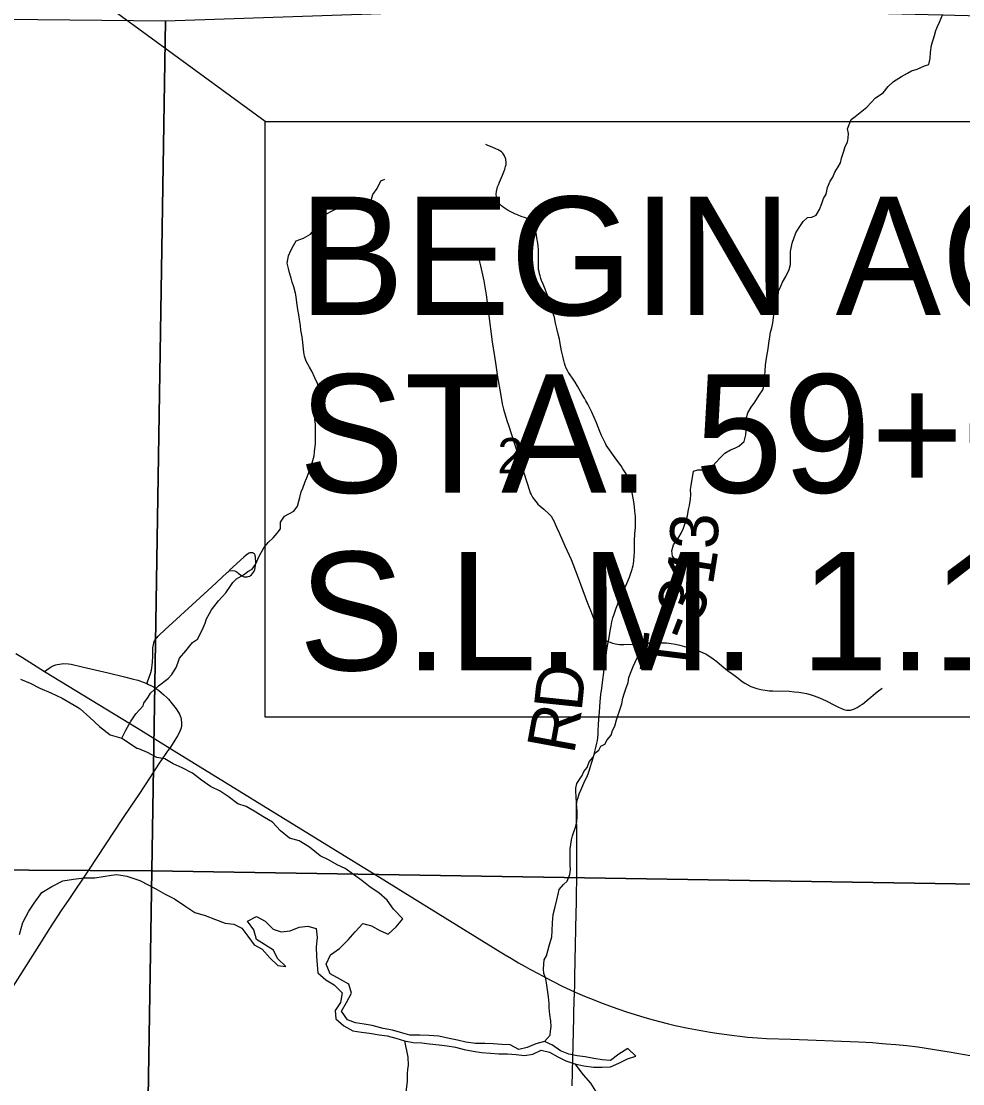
# Model space of a CAD drawing. Extents: x 0 to 34, y 0 to 22.
# Drawn here: x 23.087 to 24.201, y 15.371 to 16.628 of the extents above; entities that cross this region are included whole.
import ezdxf

# ---------------------------------------------------------------- set-up
doc = ezdxf.new("R2010")
doc.units = 0
for name, color, linetype in [('GM_X_Corporation', 7, 'Continuous'), ('GM_X_County_Road', 7, 'Continuous'), ('GM_X_Major_Lake', 7, 'Continuous'), ('GM_X_Major_River', 7, 'Continuous'), ('GM_X_Minor_River', 7, 'Continuous'), ('GM_X_Section_Text', 7, 'Continuous'), ('GM_X_Township_Road', 7, 'Continuous'), ('GM_X_Township_Road_Text', 7, 'Continuous'), ('GM_X_US_Route', 7, 'Continuous'), ('SH_Text', 7, 'Continuous')]:
    doc.layers.add(name, color=color, linetype=linetype)

msp = doc.modelspace()

# ---------------------------------------------------------------- linework, layer by layer
at = {"layer": 'GM_X_Corporation'}
for points in [[(22.2392, 16.6385), (23.2579, 16.628), (23.2418, 15.623), (22.2224, 15.6282)], [(23.2579, 16.628), (23.7676, 16.6453), (24.2698, 16.6327), (24.2658, 16.4792), (24.2407, 15.6067), (23.2418, 15.623)], [(22.2224, 15.6282), (23.2418, 15.623), (23.2254, 14.5998), (22.2045, 14.6168)], [(23.2418, 15.623), (24.2407, 15.6067), (24.2392, 15.4615), (24.2269, 14.5903), (23.2254, 14.5998)]]:
    msp.add_lwpolyline(points, close=True, dxfattribs=at)
at = {"layer": 'GM_X_County_Road'}
for points in [[(23.1352, 15.5758), (23.1379, 15.5799), (23.1441, 15.589), (23.1673, 15.6235), (23.2077, 15.6846), (23.2176, 15.6992), (23.2268, 15.713), (23.2401, 15.7336), (23.2502, 15.7488), (23.2631, 15.7678)], [(23.0733, 15.4785), (23.1115, 15.5389), (23.1206, 15.5533), (23.1352, 15.5758)]]:
    msp.add_lwpolyline(points, dxfattribs=at)
at = {"layer": 'GM_X_Major_Lake'}
for points in [[(23.0865, 15.8494), (23.0979, 15.8446), (23.1093, 15.839), (23.1226, 15.8335), (23.136, 15.8272), (23.1547, 15.816)], [(23.1547, 15.816), (23.1573, 15.8145), (23.1684, 15.8043), (23.1798, 15.7934)], [(23.1798, 15.7934), (23.1928, 15.7837), (23.2065, 15.7797), (23.2249, 15.7676)], [(23.5589, 15.4283), (23.5468, 15.4285), (23.5358, 15.4315), (23.5263, 15.4344), (23.5152, 15.4363), (23.5023, 15.4399), (23.4928, 15.4414), (23.4826, 15.4432), (23.4731, 15.4465), (23.4662, 15.4567), (23.4722, 15.467), (23.4778, 15.4781), (23.4746, 15.4887), (23.4651, 15.4943), (23.4529, 15.5011), (23.4479, 15.5124), (23.4531, 15.5235), (23.4637, 15.5311), (23.4738, 15.5411), (23.4821, 15.5507), (23.4915, 15.5606), (23.5014, 15.5577), (23.5113, 15.5521), (23.5212, 15.548), (23.5309, 15.5564), (23.5388, 15.566), (23.5277, 15.5773), (23.5201, 15.5882), (23.5102, 15.5969), (23.4999, 15.6036), (23.4903, 15.6115), (23.4804, 15.6183), (23.4705, 15.6254), (23.461, 15.6299), (23.4507, 15.6359), (23.4408, 15.6407), (23.4282, 15.6509), (23.416, 15.6584), (23.4046, 15.6613), (23.394, 15.6703), (23.3844, 15.6805), (23.3749, 15.6857), (23.3627, 15.6932), (23.3532, 15.6988), (23.3437, 15.7022), (23.3322, 15.7108), (23.3227, 15.7172), (23.3113, 15.7224), (23.3006, 15.7299), (23.2899, 15.7382), (23.2778, 15.7445), (23.2671, 15.7494), (23.2572, 15.7554), (23.2477, 15.7568), (23.2367, 15.7628), (23.2264, 15.7669), (23.2249, 15.7676)], [(23.1943, 15.6176), (23.2003, 15.6186), (23.2125, 15.6165), (23.2277, 15.6112)], [(23.0854, 15.5476), (23.0895, 15.5617), (23.0965, 15.5751), (23.1029, 15.5846), (23.1119, 15.5972), (23.1236, 15.6042), (23.1368, 15.6108), (23.1492, 15.6128), (23.1617, 15.6144), (23.1746, 15.6146), (23.1943, 15.6176)], [(23.2277, 15.6112), (23.2467, 15.6015), (23.2578, 15.5951), (23.2688, 15.5899), (23.281, 15.5816), (23.2928, 15.5734), (23.305, 15.5701), (23.3171, 15.5652), (23.3285, 15.5608), (23.3388, 15.5597), (23.3483, 15.5552), (23.3552, 15.5454), (23.3629, 15.5352), (23.3724, 15.53), (23.3812, 15.5198), (23.3907, 15.5108), (23.4002, 15.5097), (23.3906, 15.5191), (23.3856, 15.529), (23.3658, 15.5417), (23.3623, 15.5531), (23.355, 15.5633), (23.3656, 15.5687), (23.3759, 15.5631), (23.3854, 15.554), (23.3949, 15.5507), (23.4055, 15.5519), (23.4161, 15.5562), (23.4263, 15.5574), (23.4362, 15.5545), (23.4374, 15.5438), (23.436, 15.5328), (23.4365, 15.5214), (23.4373, 15.5116), (23.4382, 15.5021), (23.4477, 15.4938), (23.4576, 15.4882), (23.4668, 15.4784), (23.465, 15.4673), (23.4586, 15.4578), (23.4594, 15.4479), (23.469, 15.4397), (23.4796, 15.4337), (23.4899, 15.4322), (23.4994, 15.4308), (23.5108, 15.429), (23.5202, 15.4276), (23.5305, 15.425), (23.5404, 15.4217), (23.551, 15.4198), (23.5609, 15.4196), (23.5703, 15.4181), (23.5817, 15.4171), (23.5912, 15.416), (23.6007, 15.4142), (23.611, 15.4116), (23.6216, 15.4094), (23.6318, 15.408), (23.6421, 15.407), (23.6523, 15.4063), (23.6622, 15.4064), (23.6728, 15.4057), (23.6823, 15.4046), (23.6925, 15.4059), (23.7023, 15.4109), (23.7122, 15.4083), (23.7217, 15.4027), (23.7312, 15.3982), (23.7418, 15.3945)], [(23.7418, 15.3945), (23.7525, 15.3923), (23.7642, 15.3905), (23.7741, 15.3906), (23.7843, 15.3911), (23.7941, 15.3953), (23.8043, 15.4004), (23.8142, 15.4035), (23.8046, 15.4129), (23.794, 15.406), (23.7843, 15.3987), (23.7744, 15.3993), (23.7645, 15.4008), (23.7543, 15.403), (23.7448, 15.404), (23.7349, 15.4062), (23.725, 15.4099), (23.7155, 15.4167), (23.706, 15.4208), (23.6958, 15.4184), (23.6856, 15.4138), (23.6758, 15.4114), (23.6655, 15.417), (23.6556, 15.4173), (23.6454, 15.4184), (23.6355, 15.4187), (23.6245, 15.4186), (23.6132, 15.4204), (23.6033, 15.4226), (23.5934, 15.4244), (23.5813, 15.4273), (23.5695, 15.428), (23.5589, 15.4283)]]:
    msp.add_lwpolyline(points, dxfattribs=at)
at = {"layer": 'GM_X_Major_River'}
msp.add_lwpolyline([(23.7418, 15.3945), (23.7518, 15.3817), (23.7606, 15.3719), (23.7664, 15.3621)], dxfattribs=at)
at = {"layer": 'GM_X_Minor_River'}
for points in [[(23.8791, 16.0679), (23.8787, 16.0736), (23.8794, 16.0786), (23.8805, 16.0858), (23.8813, 16.0904), (23.8824, 16.0953), (23.8873, 16.0972), (23.8942, 16.0972), (23.8999, 16.098), (23.9048, 16.1014), (23.9089, 16.106), (23.9135, 16.1109), (23.9195, 16.1167), (23.926, 16.1205), (23.9313, 16.1228), (23.9358, 16.125), (23.9423, 16.1304), (23.9442, 16.1384), (23.9445, 16.1437), (23.9441, 16.1505), (23.9445, 16.1574), (23.9464, 16.1646), (23.9505, 16.1711), (23.9547, 16.1771), (23.96, 16.1855), (23.9641, 16.1916), (23.966, 16.1977), (23.966, 16.2022), (23.9667, 16.2091), (23.9671, 16.2136), (23.9674, 16.2212), (23.9689, 16.2315), (23.9704, 16.2403), (23.9712, 16.2467), (23.9727, 16.2543), (23.9734, 16.26), (23.9749, 16.265), (23.976, 16.2707), (23.9775, 16.2832), (23.979, 16.2882), (23.9809, 16.2969), (23.9824, 16.3018), (23.9827, 16.3083), (23.9854, 16.3144), (23.9876, 16.3189), (23.9914, 16.3258), (23.9952, 16.3338), (23.9971, 16.3399), (23.9971, 16.3459), (23.997, 16.3554), (23.9989, 16.3649), (24.0034, 16.3771), (24.0072, 16.3836), (24.0121, 16.3908), (24.017, 16.3954), (24.022, 16.3958), (24.0273, 16.3981), (24.0314, 16.4049), (24.0341, 16.4121), (24.0359, 16.4178), (24.039, 16.4231), (24.0408, 16.4311), (24.0438, 16.4384), (24.0469, 16.4433), (24.0495, 16.449), (24.0533, 16.4555), (24.0559, 16.46), (24.0574, 16.4657), (24.0601, 16.4737), (24.0616, 16.4794), (24.0642, 16.4847), (24.0653, 16.4893), (24.0657, 16.4946), (24.0642, 16.5003), (24.0687, 16.5113), (24.0732, 16.5148), (24.0793, 16.5197), (24.0872, 16.5258), (24.0974, 16.5369), (24.1065, 16.5429), (24.1126, 16.5502), (24.1186, 16.5563), (24.1281, 16.562), (24.1353, 16.5662), (24.1399, 16.5688), (24.1467, 16.5708), (24.1554, 16.5746), (24.1603, 16.5765), (24.1622, 16.5833), (24.1626, 16.5905), (24.1637, 16.5993), (24.1671, 16.6107), (24.1689, 16.6164), (24.1708, 16.6213), (24.1731, 16.6263), (24.1769, 16.6358)], [(23.2324, 15.8212), (23.2377, 15.828), (23.2404, 15.833), (23.2499, 15.8417), (23.2612, 15.8501), (23.2654, 15.8551), (23.2707, 15.8634), (23.2726, 15.8684), (23.2744, 15.8745), (23.282, 15.8829), (23.29, 15.8928), (23.296, 15.8966), (23.3013, 15.9076), (23.3051, 15.9156), (23.3066, 15.9209), (23.31, 15.927), (23.3126, 15.9316), (23.3206, 15.9422), (23.3293, 15.9517), (23.3346, 15.959), (23.3376, 15.9639), (23.3421, 15.9681), (23.3501, 15.9727), (23.3554, 15.9769), (23.3603, 15.9796), (23.3645, 15.9849), (23.3686, 15.9948), (23.3743, 16.0047), (23.3796, 16.0111), (23.3853, 16.0168), (23.3902, 16.0222), (23.394, 16.0271), (23.394, 16.0351), (23.3989, 16.0423), (23.4099, 16.0481), (23.414, 16.0542), (23.4155, 16.0599), (23.417, 16.0644), (23.4185, 16.0709), (23.4204, 16.0754), (23.4227, 16.0819), (23.4257, 16.0888), (23.428, 16.0952), (23.4313, 16.1055), (23.4336, 16.1135), (23.434, 16.1184), (23.4355, 16.1283), (23.4354, 16.1511), (23.4346, 16.1564), (23.4346, 16.1625), (23.4353, 16.1705), (23.4368, 16.1758), (23.4387, 16.1804), (23.4402, 16.1853), (23.4402, 16.1925), (23.4379, 16.199), (23.4345, 16.2058), (23.431, 16.2138), (23.4284, 16.2184), (23.4245, 16.2256), (23.4222, 16.2316), (23.4215, 16.2362), (23.4203, 16.2476), (23.4195, 16.2544), (23.418, 16.262), (23.4176, 16.2677), (23.4164, 16.275), (23.4156, 16.2803), (23.4145, 16.2867), (23.4133, 16.2951), (23.4125, 16.3015), (23.4118, 16.3061), (23.4098, 16.3133), (23.4079, 16.319), (23.4064, 16.3236), (23.4045, 16.33), (23.4033, 16.3353), (23.4018, 16.3414), (23.4033, 16.3502), (23.4063, 16.3566), (23.4093, 16.3623), (23.4127, 16.3677), (23.4211, 16.3711), (23.4294, 16.3757), (23.4354, 16.3829), (23.4426, 16.3932), (23.4483, 16.3996), (23.4544, 16.4031), (23.4635, 16.4073), (23.4737, 16.4084), (23.4783, 16.4084), (23.484, 16.4077), (23.4885, 16.4077), (23.495, 16.4115), (23.5014, 16.4172), (23.5033, 16.4225), (23.5082, 16.4298), (23.5127, 16.4389), (23.5173, 16.4408)], [(23.706, 15.4208), (23.713, 15.4285), (23.7133, 15.4331), (23.7141, 15.4388), (23.7137, 15.4449), (23.7125, 15.4529), (23.7117, 15.4608), (23.7117, 15.4658), (23.711, 15.4738), (23.709, 15.4875), (23.7075, 15.4954), (23.7052, 15.5015), (23.7048, 15.5068), (23.7059, 15.5175), (23.7085, 15.5224), (23.7116, 15.5342), (23.7146, 15.5449), (23.7153, 15.5517), (23.7157, 15.5612), (23.716, 15.5666), (23.7164, 15.5711), (23.7183, 15.5787), (23.7205, 15.5886), (23.7224, 15.5951), (23.7235, 15.6008), (23.7285, 15.6065), (23.733, 15.6107), (23.736, 15.6183), (23.7368, 15.6244), (23.7364, 15.6297), (23.7364, 15.635), (23.7363, 15.6487), (23.7371, 15.6541), (23.7382, 15.6594), (23.7393, 15.6643), (23.7431, 15.6757), (23.7442, 15.6807), (23.7449, 15.6864), (23.7449, 15.6929), (23.7438, 15.7027), (23.7434, 15.7111), (23.743, 15.716), (23.743, 15.7206), (23.7445, 15.7259), (23.7505, 15.7354), (23.7528, 15.7404), (23.7566, 15.745), (23.7588, 15.7518), (23.7637, 15.7571), (23.7656, 15.7621), (23.7702, 15.7655), (23.7728, 15.7701), (23.7774, 15.7728), (23.78, 15.7777), (23.7849, 15.7834), (23.7864, 15.7887), (23.7891, 15.7937), (23.7913, 15.8013), (23.794, 15.8097), (23.7959, 15.8154), (23.7974, 15.8203), (23.7989, 15.8272), (23.8004, 15.8321), (23.8022, 15.8382), (23.8049, 15.8454), (23.806, 15.8515), (23.8087, 15.8584), (23.8109, 15.8644), (23.8132, 15.8694), (23.8158, 15.8747), (23.8185, 15.8804), (23.8226, 15.8873), (23.8272, 15.8907), (23.8317, 15.8938), (23.8359, 15.9021), (23.8389, 15.909), (23.8423, 15.9173), (23.8445, 15.9242), (23.8464, 15.9295), (23.8487, 15.9345), (23.8521, 15.9405), (23.8562, 15.9516), (23.8593, 15.9565), (23.8623, 15.9634), (23.8638, 15.9698), (23.8649, 15.9748), (23.8645, 15.9797), (23.8645, 15.9843), (23.8614, 15.99), (23.8576, 15.9949), (23.8568, 16.0014), (23.8587, 16.0082), (23.8648, 16.0174), (23.8678, 16.0223), (23.8704, 16.028), (23.8723, 16.0341), (23.875, 16.0425), (23.8765, 16.0501), (23.8776, 16.055), (23.8787, 16.0622), (23.8791, 16.0679)], [(23.2065, 15.7797), (23.211, 15.7892), (23.2166, 15.799), (23.2229, 15.8085), (23.2316, 15.818), (23.2324, 15.8212)], [(23.5404, 15.4217), (23.5445, 15.4024), (23.5449, 15.3932), (23.5441, 15.3879), (23.5438, 15.383), (23.5438, 15.3735), (23.5419, 15.3582)]]:
    msp.add_lwpolyline(points, dxfattribs=at)
at = {"layer": 'GM_X_Township_Road'}
for points in [[(23.7436, 15.5728), (23.7439, 15.5848), (23.7443, 15.6237), (23.7442, 15.6749), (23.7441, 15.6806), (23.7439, 15.6968), (23.7441, 15.7002), (23.7443, 15.7032), (23.7449, 15.7063), (23.7459, 15.7096), (23.7472, 15.7138), (23.7492, 15.7181), (23.7528, 15.7264), (23.7568, 15.7356), (23.7576, 15.7374), (23.7585, 15.7397), (23.7593, 15.7421), (23.7602, 15.745), (23.762, 15.7512), (23.7639, 15.7576), (23.7656, 15.7639), (23.7668, 15.7686), (23.7681, 15.7739), (23.7686, 15.7768), (23.7691, 15.7803), (23.7695, 15.785), (23.7697, 15.7897), (23.77, 15.7951), (23.7704, 15.8024), (23.7711, 15.8108), (23.7721, 15.8226), (23.7729, 15.8313), (23.7738, 15.8388), (23.775, 15.8488), (23.7761, 15.8572), (23.7772, 15.866), (23.7779, 15.871), (23.779, 15.8779), (23.7803, 15.8866), (23.7811, 15.8908), (23.7817, 15.8946), (23.7828, 15.9013), (23.7837, 15.9067), (23.7848, 15.9124), (23.7858, 15.9172), (23.787, 15.9221), (23.7883, 15.9265), (23.7908, 15.9336), (23.7916, 15.9356), (23.7937, 15.9406), (23.7973, 15.9487), (23.8036, 15.9627), (23.8066, 15.9701), (23.8087, 15.9762), (23.8098, 15.9795), (23.8103, 15.9813), (23.811, 15.9838), (23.8113, 15.9862), (23.8118, 15.9895), (23.8122, 15.9954), (23.8124, 15.9994), (23.8125, 16.0044), (23.8126, 16.0114), (23.8127, 16.0155), (23.8128, 16.0191), (23.813, 16.0218), (23.8133, 16.0252), (23.8135, 16.0288), (23.8137, 16.0325), (23.8138, 16.0366), (23.8136, 16.0418), (23.8131, 16.0482), (23.8126, 16.0533), (23.8118, 16.0593), (23.8111, 16.0634), (23.8102, 16.0677), (23.8093, 16.0717), (23.8083, 16.0757), (23.8073, 16.0796), (23.806, 16.084), (23.8045, 16.0882), (23.8029, 16.0914), (23.8018, 16.0935), (23.8003, 16.0958), (23.7987, 16.0984), (23.7967, 16.1016), (23.7918, 16.1086), (23.7876, 16.1141), (23.7829, 16.1208), (23.7792, 16.1263), (23.7782, 16.1281), (23.7765, 16.1312), (23.7749, 16.1343), (23.7734, 16.1377), (23.7715, 16.1422), (23.7695, 16.1475), (23.7675, 16.1526), (23.7647, 16.159), (23.7619, 16.1654), (23.7597, 16.17), (23.7573, 16.1746), (23.7551, 16.1787), (23.7534, 16.1817), (23.7505, 16.1863), (23.745, 16.1961), (23.7423, 16.2007), (23.7393, 16.2054), (23.7365, 16.2093), (23.7346, 16.2121), (23.7332, 16.2146), (23.7317, 16.2174), (23.7306, 16.2203), (23.7296, 16.223), (23.7289, 16.2262), (23.7277, 16.2314), (23.7264, 16.2378), (23.7247, 16.2465), (23.7237, 16.2515), (23.7223, 16.2575), (23.7207, 16.2643), (23.7193, 16.2706), (23.7178, 16.2773), (23.7167, 16.2808), (23.7115, 16.2977), (23.7082, 16.3076), (23.707, 16.3108), (23.7047, 16.3165), (23.7027, 16.3211), (23.7019, 16.3232), (23.7009, 16.3265), (23.7003, 16.3289), (23.6997, 16.3317), (23.6992, 16.3341), (23.699, 16.3371), (23.699, 16.3544), (23.6989, 16.3577), (23.6985, 16.3617), (23.6982, 16.365), (23.6972, 16.3714), (23.6966, 16.375), (23.6959, 16.3786), (23.6952, 16.3814), (23.6942, 16.384), (23.6931, 16.3863), (23.6921, 16.3882), (23.6908, 16.3899), (23.69, 16.3909), (23.6884, 16.3924), (23.6862, 16.3938), (23.6838, 16.3949), (23.6787, 16.3968), (23.6748, 16.3982), (23.6709, 16.3998), (23.667, 16.4018), (23.6632, 16.4038), (23.6596, 16.4059), (23.6574, 16.4075), (23.6552, 16.4092), (23.6534, 16.4111), (23.6517, 16.4131), (23.6508, 16.4144), (23.65, 16.4162), (23.6496, 16.4177), (23.6492, 16.4199), (23.649, 16.4232), (23.6493, 16.4262), (23.65, 16.4298), (23.6507, 16.4316), (23.6517, 16.4342), (23.6529, 16.4372), (23.654, 16.4399), (23.6564, 16.4455), (23.658, 16.4495), (23.6592, 16.4525), (23.6601, 16.4556), (23.6606, 16.458), (23.6607, 16.4601), (23.6603, 16.4645), (23.6596, 16.4664), (23.6588, 16.4685), (23.6578, 16.4704), (23.6568, 16.4717), (23.6553, 16.4731), (23.6534, 16.4743), (23.6514, 16.4754), (23.6449, 16.4783), (23.6384, 16.4809), (23.6368, 16.4816)], [(23.629, 16.3447), (23.6306, 16.3383), (23.6343, 16.3205), (23.637, 16.3038), (23.64, 16.2823), (23.6443, 16.2483), (23.648, 16.2235), (23.6505, 16.2072), (23.6539, 16.1873), (23.6561, 16.1752), (23.6576, 16.1689), (23.6595, 16.162), (23.6616, 16.1555), (23.6635, 16.1498), (23.6715, 16.1256), (23.6786, 16.1033), (23.6882, 16.0727), (23.6893, 16.0699), (23.6904, 16.0677), (23.6921, 16.0647), (23.6939, 16.0619), (23.6961, 16.059), (23.6983, 16.0566), (23.701, 16.054), (23.7053, 16.0504), (23.7117, 16.0447), (23.7138, 16.0422), (23.716, 16.0386), (23.7174, 16.0359), (23.7189, 16.0328), (23.7204, 16.0294), (23.7235, 16.0224), (23.7303, 16.0073), (23.7378, 15.991), (23.7449, 15.9724), (23.7516, 15.9542), (23.7571, 15.9392), (23.7609, 15.93), (23.7644, 15.9203), (23.7677, 15.9116), (23.7702, 15.9048), (23.7721, 15.9016), (23.774, 15.8992), (23.7756, 15.8976), (23.7771, 15.8963), (23.7787, 15.8953), (23.781, 15.8942), (23.7836, 15.8932), (23.7865, 15.8922), (23.7902, 15.8912), (23.7947, 15.8904), (23.7999, 15.8903), (23.8119, 15.8907), (23.8291, 15.8921), (23.8371, 15.8925), (23.8446, 15.8926), (23.8503, 15.8924), (23.8559, 15.8918), (23.8611, 15.891), (23.8661, 15.8898), (23.8718, 15.8881), (23.8774, 15.8865), (23.8832, 15.8847), (23.8882, 15.883), (23.8929, 15.8812), (23.8974, 15.8789), (23.9016, 15.8763), (23.9054, 15.8735), (23.9097, 15.8703), (23.9156, 15.8652), (23.9226, 15.8598), (23.9288, 15.8553), (23.9349, 15.8508), (23.9399, 15.8468), (23.9431, 15.8446), (23.9464, 15.8427), (23.95, 15.8409), (23.9534, 15.8396), (23.9571, 15.8385), (23.9618, 15.8374), (23.9668, 15.8365), (23.9718, 15.8358), (23.9761, 15.8356), (23.9954, 15.8352), (24.0013, 15.8346), (24.0066, 15.834), (24.0116, 15.8333), (24.016, 15.8324), (24.0203, 15.8313), (24.0251, 15.8298), (24.0313, 15.8273), (24.0392, 15.8239), (24.049, 15.8188), (24.0535, 15.8165), (24.0573, 15.8148), (24.0599, 15.8137), (24.0631, 15.813), (24.0656, 15.8128), (24.0679, 15.813), (24.0702, 15.8135), (24.0725, 15.8143), (24.0757, 15.8159), (24.0795, 15.8184), (24.082, 15.8201), (24.0871, 15.8242), (24.0993, 15.8346), (24.1009, 15.8358), (24.1052, 15.8388)], [(23.236, 15.8442), (23.2379, 15.8494), (23.2406, 15.8573), (23.2413, 15.86), (23.2418, 15.863), (23.2423, 15.8659), (23.2426, 15.8694), (23.2429, 15.8766), (23.2432, 15.8867), (23.2441, 15.8921), (23.2443, 15.8928), (23.2452, 15.8949), (23.2459, 15.8961), (23.2492, 15.9004), (23.25, 15.9013), (23.2572, 15.908), (23.3129, 15.9586), (23.3242, 15.9692), (23.3315, 15.976), (23.3325, 15.9769), (23.3333, 15.9777), (23.3371, 15.9778), (23.3398, 15.9775), (23.3408, 15.9772), (23.3417, 15.9768), (23.3427, 15.9761), (23.344, 15.975), (23.3465, 15.9728), (23.3481, 15.9717), (23.3498, 15.9709), (23.3512, 15.9705), (23.3528, 15.9703), (23.3545, 15.9704), (23.3559, 15.9707), (23.3576, 15.9714), (23.3586, 15.9721), (23.3597, 15.973), (23.361, 15.9744), (23.3621, 15.9759), (23.3629, 15.9772), (23.3635, 15.9788), (23.3642, 15.9814), (23.3646, 15.9843), (23.3647, 15.9869), (23.3644, 15.9941), (23.3641, 15.9955), (23.3639, 15.9963), (23.3636, 15.997), (23.3632, 15.9976), (23.3626, 15.9981), (23.362, 15.9984), (23.3611, 15.9987), (23.3603, 15.9989), (23.3578, 15.9987), (23.3568, 15.9983), (23.3548, 15.9972), (23.3532, 15.996), (23.3507, 15.9939), (23.3338, 15.9782), (23.3333, 15.9777)], [(23.1149, 15.8587), (23.1203, 15.8625), (23.1228, 15.864), (23.126, 15.8655), (23.1282, 15.8663), (23.1301, 15.8669), (23.1328, 15.8674), (23.1373, 15.8679), (23.1434, 15.8676), (23.1465, 15.8671), (23.1595, 15.8642), (23.1903, 15.857), (23.2097, 15.8523), (23.2188, 15.8499), (23.2252, 15.8481), (23.2276, 15.8474), (23.2315, 15.8459), (23.236, 15.8442), (23.2381, 15.8433), (23.2408, 15.842), (23.2439, 15.8404), (23.2473, 15.8382), (23.2498, 15.8363), (23.2562, 15.8309), (23.2596, 15.8277), (23.2614, 15.8259), (23.2658, 15.8205), (23.2705, 15.8143), (23.2733, 15.8102), (23.2745, 15.808), (23.276, 15.8043), (23.2766, 15.8021), (23.2771, 15.7979), (23.2771, 15.7934), (23.2763, 15.7907), (23.2746, 15.7867), (23.2723, 15.7824), (23.2678, 15.7752), (23.2631, 15.7678)], [(23.739, 15.3684), (23.7406, 15.4488), (23.7407, 15.4556), (23.7416, 15.4799), (23.7418, 15.4861), (23.7421, 15.4978), (23.7436, 15.5728)]]:
    msp.add_lwpolyline(points, dxfattribs=at)
at = {"layer": 'GM_X_US_Route'}
for points in [[(23.081, 15.8799), (23.0888, 15.8751), (23.1149, 15.8587), (23.2257, 15.7912), (23.2631, 15.7678), (23.4591, 15.6472)], [(23.4591, 15.6472), (23.5111, 15.6152), (23.5586, 15.5858), (23.6537, 15.5271), (23.6597, 15.5235), (23.6669, 15.5192), (23.6753, 15.5142), (23.6833, 15.5096), (23.6887, 15.5066), (23.6985, 15.5013), (23.7073, 15.4966), (23.7173, 15.4915), (23.7271, 15.4866), (23.7416, 15.4799)], [(23.7416, 15.4799), (23.7453, 15.4782), (23.7533, 15.4747), (23.7674, 15.469), (23.7742, 15.4665), (23.7927, 15.4597), (23.8044, 15.4558), (23.8236, 15.4498), (23.833, 15.4471), (23.8527, 15.4419), (23.8607, 15.44), (23.8759, 15.4367), (23.8846, 15.435), (23.9019, 15.4319), (23.91, 15.4307), (23.9304, 15.4279), (23.9371, 15.4272), (23.9463, 15.4262), (23.9578, 15.4253), (23.9687, 15.4247), (23.9973, 15.4236), (24.0775, 15.4207), (24.086, 15.4203), (24.0938, 15.4197), (24.1013, 15.4192), (24.11, 15.4184), (24.1215, 15.4174), (24.1343, 15.4161), (24.1474, 15.4145), (24.1746, 15.4104), (24.187, 15.4085), (24.2093, 15.4044)]]:
    msp.add_lwpolyline(points, dxfattribs=at)
at = {"layer": 'SH_Text'}
msp.add_line((23.3758, 16.509), (22.3474, 17.2614), dxfattribs=at)
msp.add_lwpolyline([(23.3758, 16.509), (25.2602, 16.509), (25.2602, 15.8046), (23.3758, 15.8046)], close=True, dxfattribs=at)

# ---------------------------------------------------------------- texts
at = {"layer": 'GM_X_Section_Text'}
msp.add_text('2', height=0.0419, rotation=0, dxfattribs=at).set_placement((23.6504, 16.0928))
at = {"layer": 'GM_X_Township_Road_Text'}
for s, rotation, p in [('3', 89.2736, (23.9112, 16.003)), ('1', 80.961, (23.905, 15.9594)), ('3', 67.3385, (23.8875, 15.913)), ('-', 68.7103, (23.8791, 15.8916)), ('T', 82.8803, (23.8748, 15.853)), ('D', 84.0726, (23.7499, 15.8101)), ('R', 79.588, (23.7408, 15.7595))]:
    msp.add_text(s, height=0.0568, rotation=rotation, dxfattribs=at).set_placement(p)
at = {"layer": 'SH_Text'}
for s, p in [('BEGIN ACQUISITION', (23.4156, 16.28)), ('STA. 59+00.000', (23.4156, 16.07)), ('S.L.M. 1.13', (23.4156, 15.86))]:
    msp.add_text(s, height=0.14, dxfattribs=at).set_placement(p)

doc.saveas('drawing.dxf')
